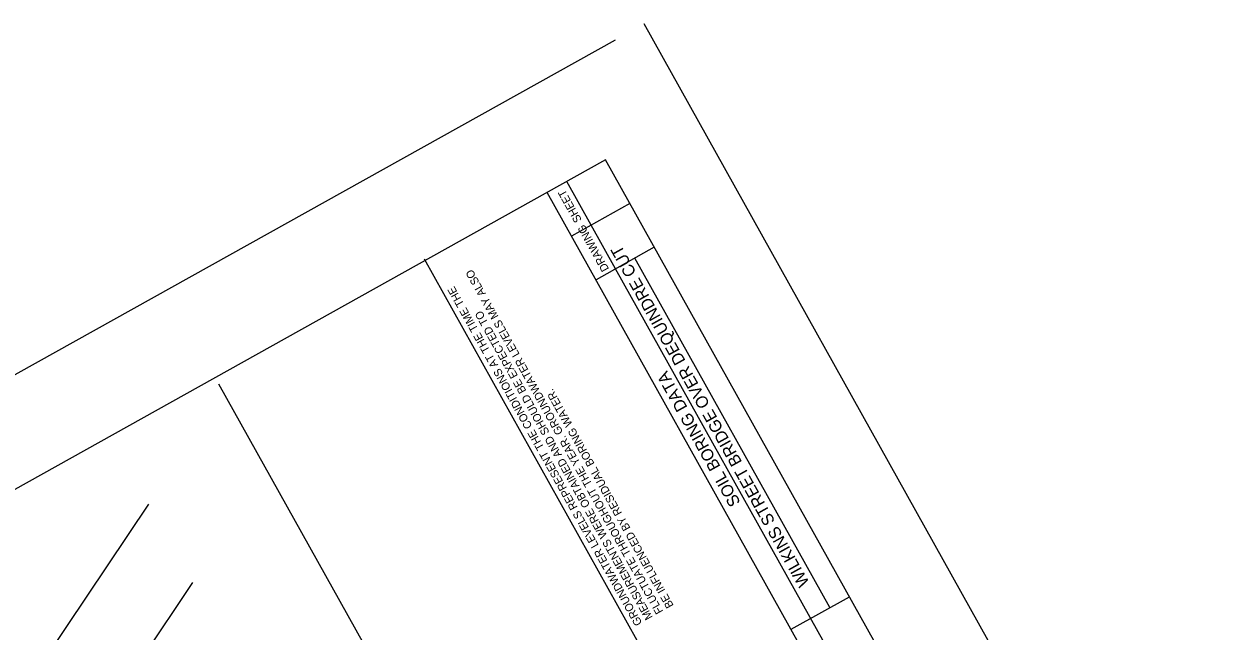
# Model space of a CAD drawing. Extents: x 13482447 to 13495412, y 324533 to 340229.
# Drawn here: x 13494341 to 13495055, y 332641 to 333005 of the extents above; entities that cross this region are included whole.
import ezdxf

# ---------------------------------------------------------------- set-up
doc = ezdxf.new("R2010")
doc.units = 0
for name, color, linetype in [('BORDER', 7, 'Continuous'), ('Default', 7, 'Continuous'), ('Level 1', 7, 'Continuous'), ('V-PROP-RWAY', 7, 'Continuous')]:
    doc.layers.add(name, color=color, linetype=linetype)

msp = doc.modelspace()

# ---------------------------------------------------------------- linework, layer by layer
at = {"layer": 'Default'}
msp.add_lwpolyline([(13494457.44, 332789.11), (13494703.36, 332348.37)], dxfattribs=at)
at = {"layer": 'Level 1'}
for p, q in [((13495412.28, 331751.04), (13494712.57, 333005.04)), ((13494695.11, 332995.29), (13493895.21, 332548.96)), ((13494689.41, 332923.41), (13493959.37, 332516.06)), ((13495330.65, 331774.2), (13494689.41, 332923.41)), ((13494695.36, 332858.02), (13494666.13, 332910.41)), ((13495295.72, 331754.71), (13494654.48, 332903.92)), ((13494704.03, 332897.21), (13494669.1, 332877.72)), ((13494718.65, 332871.01), (13494683.72, 332851.52)), ((13495223.39, 331712.33), (13494580.84, 332863.9)), ((13494823.95, 332654.93), (13494707.01, 332864.51)), ((13495007.21, 332299.13), (13494695.36, 332858.02)), ((13494800.67, 332641.94), (13494835.62, 332661.44))]:
    msp.add_line(p, q, dxfattribs=at)
at = {"layer": 'V-PROP-RWAY'}
for p, q in [((13494162.94, 332339.78), (13494415.51, 332716.95)), ((13494441.77, 332669.89), (13494189.2, 332292.72))]:
    msp.add_line(p, q, dxfattribs=at)

# ---------------------------------------------------------------- texts
at = {"layer": 'BORDER'}
for s, p in [('FLUCTUATE THROUGHOUT THE YEAR. GROUNDWATER LEVELS MAY ALSO ', (13494724.12, 332652.64)), ('GROUNDWATER LEVELS REPRESENT THE CONDITIONS AT THE TIME THE ', (13494711.55, 332645.62)), ('MEASUREMENTS WERE OBTAINED AND SHOULD BE EXPECTED TO ', (13494717.84, 332649.13)), ('BE INFLUENCED BY RESIDUAL BORING WATER. ', (13494730.41, 332656.15))]:
    msp.add_text(s, height=4.8, rotation=119.16053, dxfattribs=at).set_placement(p)
at = {"layer": 'Level 1'}
for s, height, p in [('SHEET', 4.8, (13494675.3, 332887.41)), ('DRAWING', 4.8, (13494691.65, 332858.03)), ('WILKINS STREET BRIDGE OVER DEQUINDRE CUT', 7.2, (13494811.87, 332669.74)), ('SOIL BORING DATA', 7.2, (13494770.54, 332717.93))]:
    msp.add_text(s, height=height, rotation=119.16053, dxfattribs=at).set_placement(p)

doc.saveas('drawing.dxf')
